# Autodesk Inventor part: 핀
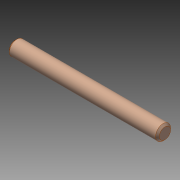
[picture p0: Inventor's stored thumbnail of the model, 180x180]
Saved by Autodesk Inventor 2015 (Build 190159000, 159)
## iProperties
Created: 2023-11
Part Number: 핀
Material: 스테인리스강
Document SubType Name: Modeling
Designer: mdu-01
Density: 1 g/cm^3
Appearance: 기본값(1)
Author: mdu-01
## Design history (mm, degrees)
sketch "스케치1"
  geometry: C1 r 2 at (0, 0); 1 further point
  constraints: 1 centre point, 1 coincident
  dimensions: "d0" = 4 diameter of C1
extrude "돌출1" new body sketch "스케치1" stored distance "d1" = 40; taper "d2" = 0 deg
chamfer "모따기1" distance "d3" = 0.5; stored, may be unused: second distance "d4" = 2, angle "d5" = 45 deg
node "솔리드1"
